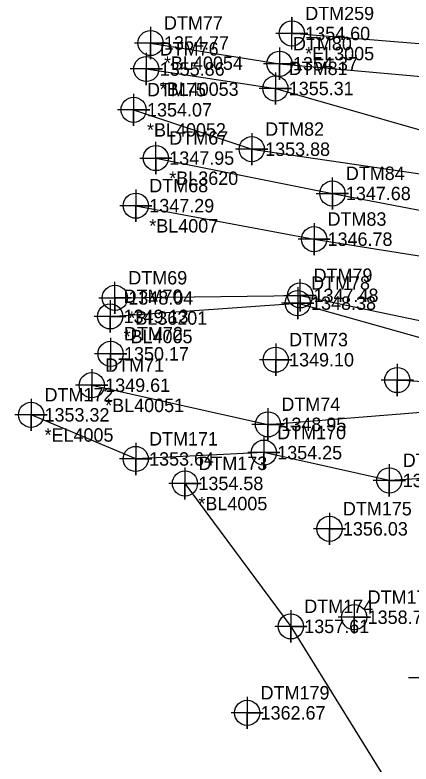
# Model space of a CAD drawing. Extents: x 1251905 to 1252853, y 859795 to 860170.
# Drawn here: x 1251904.9 to 1251978.6, y 859945.7 to 860085.2 of the extents above; entities that cross this region are included whole.
import ezdxf

# ---------------------------------------------------------------- set-up
doc = ezdxf.new("R2010")
doc.units = 0
for name, color, linetype in [('Exist DTM Breakline', 7, 'Continuous'), ('Exist DTM Breakline Cogo Comment', 7, 'Continuous'), ('Exist DTM Breakline Cogo Elevation', 7, 'Continuous'), ('Exist DTM Breakline Cogo Number', 7, 'Continuous'), ('Exist DTM Breakline Cogo Point CELL', 7, 'Continuous'), ('Exist DTM Breakline Underwater', 7, 'Continuous'), ('Exist DTM Breakline Underwater Cogo Comment', 7, 'Continuous'), ('Exist DTM Breakline Underwater Cogo Elevation', 7, 'Continuous'), ('Exist DTM Breakline Underwater Cogo Number', 7, 'Continuous'), ('Exist DTM Breakline Underwater Cogo Point CELL', 7, 'Continuous'), ('Exist DTM Regular Point CELL', 7, 'Continuous'), ('Exist DTM Regular Point Cogo Elevation', 7, 'Continuous'), ('Exist DTM Regular Point Cogo Number', 7, 'Continuous'), ('Exist Hydro Stream or Body of Water', 7, 'Continuous'), ('Exist Hydro Stream or Body of Water Cogo Comment', 7, 'Continuous'), ('Exist Hydro Stream or Body of Water Cogo Elevation', 7, 'Continuous'), ('Exist Hydro Stream or Body of Water Cogo Number', 7, 'Continuous'), ('Exist Hydro Stream or Body of Water Cogo Point CELL', 7, 'Continuous'), ('Exist Roads Soil', 7, 'Continuous'), ('Exist Roads Soil Cogo Comment', 7, 'Continuous'), ('Exist Roads Soil Cogo Elevation', 7, 'Continuous'), ('Exist Roads Soil Cogo Number', 7, 'Continuous'), ('Exist Roads Soil Cogo Point CELL', 7, 'Continuous')]:
    doc.layers.add(name, color=color, linetype=linetype)

msp = doc.modelspace()

# ---------------------------------------------------------------- linework, layer by layer
at = {"layer": 'Exist DTM Breakline'}
for points in [[(1251930.158, 860079.966), (1251954.171, 860076.105), (1251996.545, 860072.28), (1252018.833, 860066.653), (1252019.501, 860056.104), (1252023.199, 860048.714), (1252025.121, 860048.423)], [(1251929.364, 860075.129), (1251953.388, 860071.501), (1251993.329, 860060.067), (1252014.61, 860060.183), (1252018.569, 860052.108), (1252021.655, 860046.227)], [(1251926.999, 860067.532), (1251948.988, 860060.189), (1251991.758, 860053.937), (1252017.01, 860045.885), (1252022.44, 860046.144), (1252048.657, 860045.032), (1252055.807, 860052.896), (1252053.946, 860054.482), (1252047.904, 860046.493)], [(1251922.639, 860029.05), (1251957.547, 860031.512), (1251986.698, 860023.305), (1252002.628, 860018.068), (1252001.734, 860015.469), (1251976.094, 860017.179)], [(1251919.208, 860016.218), (1251952.017, 860008.928), (1251982.813, 860011.362), (1251990.283, 860012.128)], [(1252011.253, 859996.384), (1251998.853, 859999.907), (1251974.611, 859998.485), (1251951.238, 860003.66), (1251927.383, 860002.484), (1251907.913, 860010.701)], [(1251936.565, 859997.923), (1251956.275, 859971.296), (1251976.565, 859938.46), (1251988.5, 859909.824), (1252001.927, 859883.296), (1252014.633, 859879.112), (1252004.267, 859851.158)]]:
    msp.add_lwpolyline(points, dxfattribs=at)
at = {"layer": 'Exist DTM Breakline Cogo Point CELL'}
for points in [[(1251930.158, 860082.966), (1251930.158, 860076.966), (1251930.158, 860079.966), (1251933.158, 860079.966), (1251927.158, 860079.966)], [(1251929.364, 860078.129), (1251929.364, 860072.129), (1251929.364, 860075.129), (1251932.364, 860075.129), (1251926.364, 860075.129)], [(1251954.171, 860079.105), (1251954.171, 860073.105), (1251954.171, 860076.105), (1251957.171, 860076.105), (1251951.171, 860076.105)], [(1251953.388, 860074.501), (1251953.388, 860068.501), (1251953.388, 860071.501), (1251956.388, 860071.501), (1251950.388, 860071.501)], [(1251926.999, 860070.532), (1251926.999, 860064.532), (1251926.999, 860067.532), (1251929.999, 860067.532), (1251923.999, 860067.532)], [(1251948.988, 860063.189), (1251948.988, 860057.189), (1251948.988, 860060.189), (1251951.988, 860060.189), (1251945.988, 860060.189)], [(1251957.547, 860034.512), (1251957.547, 860028.512), (1251957.547, 860031.512), (1251960.547, 860031.512), (1251954.547, 860031.512)], [(1251922.639, 860032.05), (1251922.639, 860026.05), (1251922.639, 860029.05), (1251925.639, 860029.05), (1251919.639, 860029.05)], [(1251976.094, 860020.179), (1251976.094, 860014.179), (1251976.094, 860017.179), (1251979.094, 860017.179), (1251973.094, 860017.179)], [(1251919.208, 860019.218), (1251919.208, 860013.218), (1251919.208, 860016.218), (1251922.208, 860016.218), (1251916.208, 860016.218)], [(1251907.913, 860013.701), (1251907.913, 860007.701), (1251907.913, 860010.701), (1251910.913, 860010.701), (1251904.913, 860010.701)], [(1251952.017, 860011.928), (1251952.017, 860005.928), (1251952.017, 860008.928), (1251955.017, 860008.928), (1251949.017, 860008.928)], [(1251927.383, 860005.484), (1251927.383, 859999.484), (1251927.383, 860002.484), (1251930.383, 860002.484), (1251924.383, 860002.484)], [(1251951.238, 860006.66), (1251951.238, 860000.66), (1251951.238, 860003.66), (1251954.238, 860003.66), (1251948.238, 860003.66)], [(1251974.611, 860001.485), (1251974.611, 859995.485), (1251974.611, 859998.485), (1251977.611, 859998.485), (1251971.611, 859998.485)], [(1251936.565, 860000.923), (1251936.565, 859994.923), (1251936.565, 859997.923), (1251939.565, 859997.923), (1251933.565, 859997.923)], [(1251956.275, 859974.296), (1251956.275, 859968.296), (1251956.275, 859971.296), (1251959.275, 859971.296), (1251953.275, 859971.296)]]:
    msp.add_lwpolyline(points, dxfattribs=at)
for centre in [(1251930.158, 860079.966), (1251954.171, 860076.105), (1251929.364, 860075.129), (1251953.388, 860071.501), (1251926.999, 860067.532), (1251948.988, 860060.189), (1251957.547, 860031.512), (1251922.639, 860029.05), (1251976.094, 860017.179), (1251919.208, 860016.218), (1251907.913, 860010.701), (1251952.017, 860008.928), (1251951.238, 860003.66), (1251927.383, 860002.484), (1251936.565, 859997.923), (1251974.611, 859998.485), (1251956.275, 859971.296)]:
    msp.add_circle(centre, 2.344, dxfattribs=at)
at = {"layer": 'Exist DTM Breakline Underwater'}
msp.add_lwpolyline([(1251927.42, 860049.663), (1251960.607, 860043.428), (1251991.544, 860038.543), (1252023.095, 860021.002), (1252051.108, 860015.006), (1252097.444, 860018.35), (1252136.124, 860025.415), (1252179.795, 860024.836), (1252209.042, 860015.729)], dxfattribs=at)
at = {"layer": 'Exist DTM Breakline Underwater Cogo Point CELL'}
for points in [[(1251927.42, 860052.663), (1251927.42, 860046.663), (1251927.42, 860049.663), (1251930.42, 860049.663), (1251924.42, 860049.663)], [(1251960.607, 860046.428), (1251960.607, 860040.428), (1251960.607, 860043.428), (1251963.607, 860043.428), (1251957.607, 860043.428)]]:
    msp.add_lwpolyline(points, dxfattribs=at)
for centre in [(1251927.42, 860049.663), (1251960.607, 860043.428)]:
    msp.add_circle(centre, 2.344, dxfattribs=at)
at = {"layer": 'Exist DTM Regular Point CELL'}
for points in [[(1251922.713, 860025.073), (1251922.713, 860019.073), (1251922.713, 860022.073), (1251925.713, 860022.073), (1251919.713, 860022.073)], [(1251953.45, 860023.971), (1251953.45, 860017.971), (1251953.45, 860020.971), (1251956.45, 860020.971), (1251950.45, 860020.971)], [(1251963.469, 859992.466), (1251963.469, 859986.466), (1251963.469, 859989.466), (1251966.469, 859989.466), (1251960.469, 859989.466)], [(1251968.079, 859975.999), (1251968.079, 859969.999), (1251968.079, 859972.999), (1251971.079, 859972.999), (1251965.079, 859972.999)], [(1251981.162, 859964.689), (1251981.162, 859958.689), (1251981.162, 859961.689), (1251984.162, 859961.689), (1251978.162, 859961.689)], [(1251948.146, 859958.187), (1251948.146, 859952.187), (1251948.146, 859955.187), (1251951.146, 859955.187), (1251945.146, 859955.187)]]:
    msp.add_lwpolyline(points, dxfattribs=at)
for centre in [(1251922.713, 860022.073), (1251953.45, 860020.971), (1251963.469, 859989.466), (1251968.079, 859972.999), (1251948.146, 859955.187)]:
    msp.add_circle(centre, 2.344, dxfattribs=at)
at = {"layer": 'Exist Hydro Stream or Body of Water'}
for points in [[(1251931.145, 860058.535), (1251964.012, 860051.945), (1251993.851, 860046.208), (1252023.877, 860040.562), (1252046.52, 860034.729)], [(1251923.519, 860032.492), (1251957.999, 860032.964), (1251987.699, 860026.743), (1252004.412, 860018.883), (1252004.612, 860014.582), (1251994.716, 860013.049), (1252010.915, 860007.676), (1252019.462, 860003.97), (1252019.665, 860004.195), (1252046.38, 860003.539), (1252090.782, 859996.797), (1252140.715, 860010.791), (1252179.759, 860006.581), (1252205.549, 860000.12)]]:
    msp.add_lwpolyline(points, dxfattribs=at)
at = {"layer": 'Exist Hydro Stream or Body of Water Cogo Point CELL'}
for points in [[(1251928.145, 860058.535), (1251934.145, 860058.535), (1251931.145, 860058.535), (1251931.145, 860055.535), (1251931.145, 860061.535)], [(1251961.012, 860051.945), (1251967.012, 860051.945), (1251964.012, 860051.945), (1251964.012, 860048.945), (1251964.012, 860054.945)], [(1251920.519, 860032.492), (1251926.519, 860032.492), (1251923.519, 860032.492), (1251923.519, 860029.492), (1251923.519, 860035.492)], [(1251954.999, 860032.964), (1251960.999, 860032.964), (1251957.999, 860032.964), (1251957.999, 860029.964), (1251957.999, 860035.964)]]:
    msp.add_lwpolyline(points, dxfattribs=at)
for centre in [(1251931.145, 860058.535), (1251964.012, 860051.945), (1251923.519, 860032.492), (1251957.999, 860032.964)]:
    msp.add_circle(centre, 2.344, dxfattribs=at)
at = {"layer": 'Exist Roads Soil'}
msp.add_lwpolyline([(1252027.154, 860067.333), (1252015.44, 860074.915), (1251989.358, 860079.095), (1251956.453, 860081.754)], dxfattribs=at)
at = {"layer": 'Exist Roads Soil Cogo Point CELL'}
msp.add_lwpolyline([(1251956.453, 860078.754), (1251956.453, 860084.754), (1251956.453, 860081.754), (1251959.453, 860081.754), (1251953.453, 860081.754)], dxfattribs=at)
msp.add_circle((1251956.453, 860081.754), 2.344, dxfattribs=at)

# ---------------------------------------------------------------- texts
at = {"layer": 'Exist DTM Breakline Cogo Comment'}
for s, p in [('*BL40054', (1251932.658, 860074.966)), ('*BL40053', (1251931.864, 860070.129)), ('*BL40052', (1251929.499, 860062.532)), ('*BL4005', (1251925.139, 860024.05)), ('*BL40051', (1251921.708, 860011.218)), ('*EL4005', (1251910.413, 860005.701)), ('*BL4005', (1251939.065, 859992.923))]:
    msp.add_text(s, height=2.5, dxfattribs=at).set_placement(p)
at = {"layer": 'Exist DTM Breakline Cogo Elevation'}
for s, p in [('1354.77', (1251932.658, 860078.716)), ('1354.37', (1251956.671, 860074.855)), ('1355.86', (1251931.864, 860073.879)), ('1355.31', (1251955.888, 860070.251)), ('1354.07', (1251929.499, 860066.282)), ('1353.88', (1251951.488, 860058.939)), ('1348.38', (1251960.047, 860030.262)), ('1349.13', (1251925.139, 860027.8)), ('1349.61', (1251921.708, 860014.968)), ('1353.32', (1251910.413, 860009.451)), ('1348.95', (1251954.517, 860007.678)), ('1354.25', (1251953.738, 860002.41)), ('1353.64', (1251929.883, 860001.234)), ('1354.58', (1251939.065, 859996.673)), ('1354.68', (1251977.111, 859997.235)), ('1357.61', (1251958.775, 859970.046))]:
    msp.add_text(s, height=2.5, dxfattribs=at).set_placement(p)
at = {"layer": 'Exist DTM Breakline Cogo Number'}
for s, p in [('DTM77', (1251932.658, 860082.466)), ('DTM80', (1251956.671, 860078.605)), ('DTM76', (1251931.864, 860077.629)), ('DTM81', (1251955.888, 860074.001)), ('DTM75', (1251929.499, 860070.032)), ('DTM82', (1251951.488, 860062.689)), ('DTM78', (1251960.047, 860034.012)), ('DTM70', (1251925.139, 860031.55)), ('DTM71', (1251921.708, 860018.718)), ('DTM172', (1251910.413, 860013.201)), ('DTM74', (1251954.517, 860011.428)), ('DTM170', (1251953.738, 860006.16)), ('DTM171', (1251929.883, 860004.984)), ('DTM173', (1251939.065, 860000.423)), ('DTM169', (1251977.111, 860000.985)), ('DTM174', (1251958.775, 859973.796))]:
    msp.add_text(s, height=2.5, dxfattribs=at).set_placement(p)
at = {"layer": 'Exist DTM Breakline Underwater Cogo Comment'}
msp.add_text('*BL4007', height=2.5, dxfattribs=at).set_placement((1251929.92, 860044.663))
at = {"layer": 'Exist DTM Breakline Underwater Cogo Elevation'}
for s, p in [('1347.29', (1251929.92, 860048.413)), ('1346.78', (1251963.107, 860042.178))]:
    msp.add_text(s, height=2.5, dxfattribs=at).set_placement(p)
at = {"layer": 'Exist DTM Breakline Underwater Cogo Number'}
for s, p in [('DTM68', (1251929.92, 860052.163)), ('DTM83', (1251963.107, 860045.928))]:
    msp.add_text(s, height=2.5, dxfattribs=at).set_placement(p)
at = {"layer": 'Exist DTM Regular Point Cogo Elevation'}
for s, p in [('1350.17', (1251925.213, 860020.823)), ('1349.10', (1251955.95, 860019.721)), ('1356.03', (1251965.969, 859988.216)), ('1358.70', (1251970.579, 859971.749)), ('1362.67', (1251950.646, 859953.937))]:
    msp.add_text(s, height=2.5, dxfattribs=at).set_placement(p)
at = {"layer": 'Exist DTM Regular Point Cogo Number'}
for s, p in [('DTM72', (1251925.213, 860024.573)), ('DTM73', (1251955.95, 860023.471)), ('DTM175', (1251965.969, 859991.966)), ('DTM176', (1251970.579, 859975.499)), ('DTM179', (1251950.646, 859957.687))]:
    msp.add_text(s, height=2.5, dxfattribs=at).set_placement(p)
at = {"layer": 'Exist Hydro Stream or Body of Water Cogo Comment'}
for s, p in [('*BL3620', (1251933.645, 860053.535)), ('*BL36201', (1251926.019, 860027.492))]:
    msp.add_text(s, height=2.5, dxfattribs=at).set_placement(p)
at = {"layer": 'Exist Hydro Stream or Body of Water Cogo Elevation'}
for s, p in [('1347.95', (1251933.645, 860057.285)), ('1347.68', (1251966.512, 860050.695)), ('1348.04', (1251926.019, 860031.242)), ('1347.48', (1251960.499, 860031.714))]:
    msp.add_text(s, height=2.5, dxfattribs=at).set_placement(p)
at = {"layer": 'Exist Hydro Stream or Body of Water Cogo Number'}
for s, p in [('DTM67', (1251933.645, 860061.035)), ('DTM84', (1251966.512, 860054.445)), ('DTM69', (1251926.019, 860034.992)), ('DTM79', (1251960.499, 860035.464))]:
    msp.add_text(s, height=2.5, dxfattribs=at).set_placement(p)
at = {"layer": 'Exist Roads Soil Cogo Comment'}
msp.add_text('*EL3005', height=2.5, dxfattribs=at).set_placement((1251958.953, 860076.754))
at = {"layer": 'Exist Roads Soil Cogo Elevation'}
msp.add_text('1354.60', height=2.5, dxfattribs=at).set_placement((1251958.953, 860080.504))
at = {"layer": 'Exist Roads Soil Cogo Number'}
msp.add_text('DTM259', height=2.5, dxfattribs=at).set_placement((1251958.953, 860084.254))

doc.saveas('drawing.dxf')
